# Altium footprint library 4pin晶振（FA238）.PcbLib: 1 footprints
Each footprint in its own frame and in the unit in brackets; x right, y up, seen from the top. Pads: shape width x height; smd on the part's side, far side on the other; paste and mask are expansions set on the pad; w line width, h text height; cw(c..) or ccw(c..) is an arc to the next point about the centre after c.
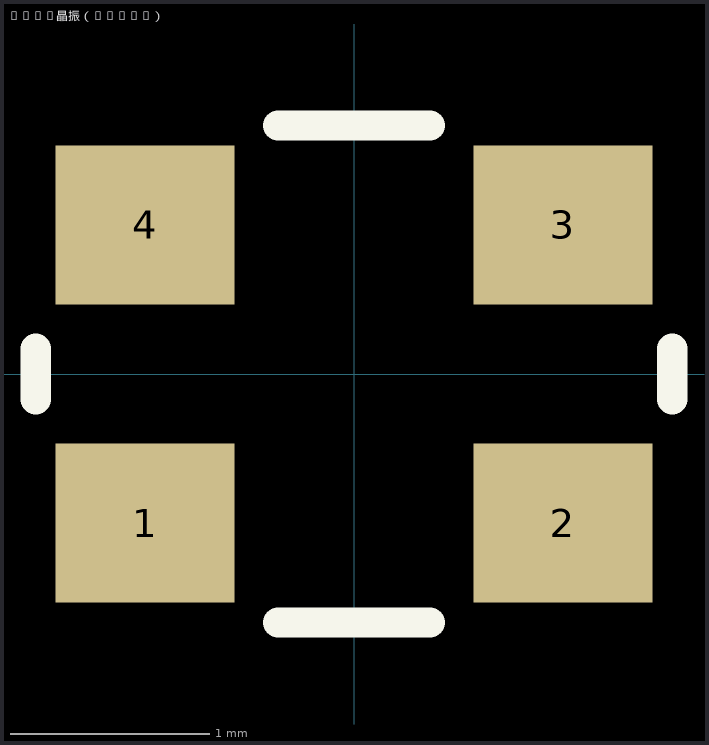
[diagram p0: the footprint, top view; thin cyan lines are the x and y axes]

## 4pin晶振（FA238） [mm] "4pin晶振（FA238）"
pads (4):
  rect 0.9x0.8 smd: 1(-1.05,-0.75) 2(1.05,-0.75) 3(1.05,0.75) 4(-1.05,0.75)
Top Overlay:
  lines w0.152: -1.6,-0.127 -1.6,0.127 ; -0.381,-1.25 0.381,-1.25 ; -0.381,1.25 0.381,1.25 ; 1.6,-0.127 1.6,0.127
